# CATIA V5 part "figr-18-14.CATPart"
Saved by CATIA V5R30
Part number: Part1
Bounding box of the stored display mesh (mm): x -135 to 135, y -70 to 70, z 0 to 30
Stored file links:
  D:\PROJECTS\CATIA V56R 2020\Resources\Parts File\c18_catia_v6_6r2020_prt\figr-18-14.CATPart
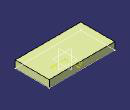
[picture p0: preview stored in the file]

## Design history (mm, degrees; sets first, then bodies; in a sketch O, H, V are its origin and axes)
Body1 (main body)
  Sketch1 on xy-plane, origin (0, 0, 0), H (1, 0, 0), V (0, 1, 0)
    line L1 (135, 70) -> (135, -70)
    line L2 (135, -70) -> (-135, -70)
    line L3 (-135, -70) -> (-135, 70)
    line L4 (-135, 70) -> (135, 70)
    length L2 = 270
    length L1 = 140
    vertical: L1 V, L3 V
    horizontal: L2 H, L4 H
    equidistance: L1 L3 O, L2 L4 O
  Extrude1: Element1 Sketch1, Lim1 30, Lim2 0
  DatumSurface1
